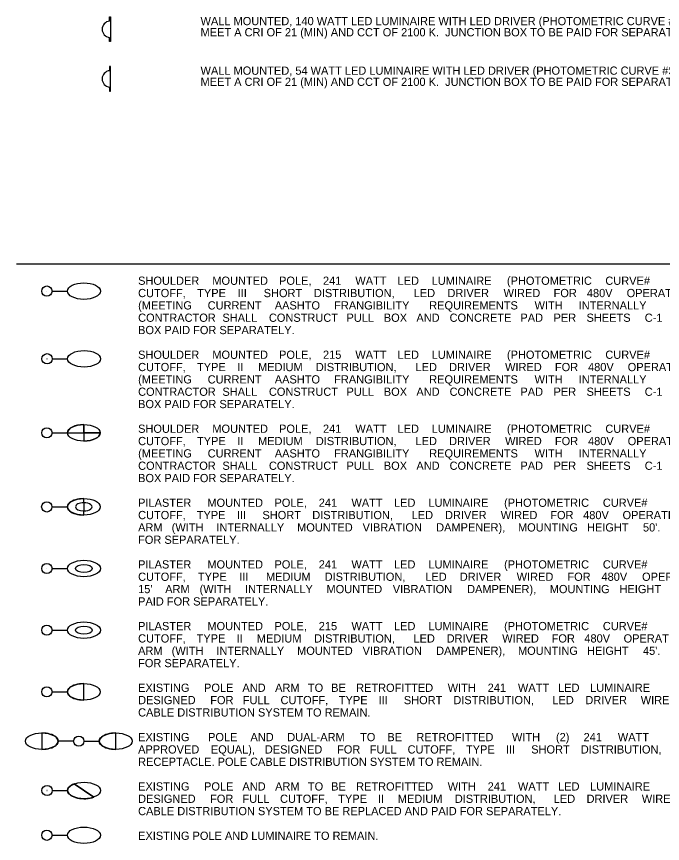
# Model space of a CAD drawing. Extents: x -1500 to -654, y -278 to 331.
# Drawn here: x -1424.2 to -1188.7, y 29.1 to 330.8 of the extents above; entities that cross this region are included whole.
import ezdxf

# ---------------------------------------------------------------- set-up
doc = ezdxf.new("R2010")
doc.units = 0
for name, color, linetype in [('AdhocPoint_dp', 7, 'Continuous'), ('Default', 7, 'Continuous'), ('Logo_dp', 7, 'Continuous'), ('Miscellaneous3', 7, 'Continuous'), ('SheetBorder_dp', 7, 'Continuous'), ('SheetLines_dp', 7, 'Continuous'), ('TextMisc', 7, 'Continuous')]:
    doc.layers.add(name, color=color, linetype=linetype)

msp = doc.modelspace()

# ---------------------------------------------------------------- linework, layer by layer
at = {"layer": 'AdhocPoint_dp'}
for p, q in [((-1390.27, 329.13), (-1390.27, 330.65)), ((-1390.27, 330.65), (-1389.97, 330.65)), ((-1389.97, 330.65), (-1389.97, 321.65)), ((-1390.27, 321.65), (-1390.27, 323.16)), ((-1389.97, 321.65), (-1390.27, 321.65)), ((-1390.27, 312.57), (-1390.27, 311.05)), ((-1389.97, 312.57), (-1390.27, 312.57)), ((-1389.97, 303.57), (-1389.97, 312.57)), ((-1390.27, 305.08), (-1390.27, 303.57)), ((-1390.27, 303.57), (-1389.97, 303.57))]:
    msp.add_line(p, q, dxfattribs=at)
for centre in [(-1389.97, 326.15), (-1389.97, 308.07)]:
    msp.add_arc(centre, 3, 95.7392, 264.2608, dxfattribs=at)
at = {"layer": 'Logo_dp'}
msp.add_line((-1411.26, 32.11), (-1405.63, 32.11), dxfattribs=at)
msp.add_circle((-1413.13, 32.11), 1.88, dxfattribs=at)
msp.add_ellipse((-1399.63, 32.11), major_axis=(6, 0), ratio=0.5, dxfattribs=at)
at = {"layer": 'Miscellaneous3'}
msp.add_line((-1424.17, 240.54), (-654.17, 240.54), dxfattribs=at)
at = {"layer": 'SheetLines_dp'}
for p, q in [((-1413.16, 230.6), (-1413.16, 230.67)), ((-1413.16, 230.67), (-1413.09, 230.67)), ((-1413.09, 230.6), (-1413.16, 230.67)), ((-1413.09, 230.6), (-1413.16, 230.6)), ((-1413.09, 230.67), (-1413.09, 230.6)), ((-1413.08, 205.89), (-1413.08, 205.97)), ((-1413.08, 205.97), (-1413.01, 205.97)), ((-1413.01, 205.89), (-1413.08, 205.97)), ((-1413.01, 205.89), (-1413.08, 205.89)), ((-1413.01, 205.97), (-1413.01, 205.89)), ((-1413.16, 129.39), (-1413.16, 129.47)), ((-1413.16, 129.47), (-1413.09, 129.47)), ((-1413.09, 129.39), (-1413.16, 129.47)), ((-1413.09, 129.39), (-1413.16, 129.39)), ((-1413.09, 129.47), (-1413.09, 129.39)), ((-1413.16, 106.89), (-1413.16, 106.97)), ((-1413.16, 106.97), (-1413.09, 106.97)), ((-1413.09, 106.89), (-1413.16, 106.97)), ((-1413.09, 106.89), (-1413.16, 106.89)), ((-1413.09, 106.97), (-1413.09, 106.89)), ((-1413.08, 48.39), (-1413.08, 48.47)), ((-1413.08, 48.47), (-1413.01, 48.47)), ((-1413.01, 48.39), (-1413.08, 48.47)), ((-1413.01, 48.39), (-1413.08, 48.39)), ((-1413.01, 48.47), (-1413.01, 48.39))]:
    msp.add_line(p, q, dxfattribs=at)
at = {"layer": 'TextMisc'}
for p, q in [((-1411.25, 230.63), (-1405.63, 230.63)), ((-1411.17, 205.93), (-1405.55, 205.93)), ((-1399.64, 181.93), (-1399.64, 175.93)), ((-1399.64, 178.93), (-1399.64, 181.93)), ((-1411.25, 178.93), (-1405.63, 178.93)), ((-1405.63, 178.93), (-1393.65, 178.93)), ((-1405.63, 178.93), (-1399.64, 178.93)), ((-1393.65, 178.93), (-1399.64, 178.93)), ((-1399.64, 178.93), (-1399.64, 175.93)), ((-1399.67, 153.43), (-1399.67, 154.93)), ((-1411.29, 151.91), (-1405.66, 151.92)), ((-1399.67, 153.43), (-1399.66, 150.43)), ((-1399.66, 148.93), (-1399.66, 150.43)), ((-1411.25, 129.43), (-1405.63, 129.43)), ((-1411.25, 106.93), (-1405.63, 106.93)), ((-1399.64, 81.43), (-1399.64, 87.43)), ((-1411.25, 84.43), (-1405.63, 84.43)), ((-1414.98, 69.43), (-1414.98, 63.43)), ((-1388.01, 63.43), (-1388.01, 69.43)), ((-1403.37, 66.43), (-1408.99, 66.43)), ((-1399.62, 66.43), (-1394, 66.43)), ((-1411.17, 48.43), (-1405.55, 48.43)), ((-1403.11, 50.84), (-1395.98, 46.02)), ((-1395.98, 46.02), (-1403.11, 50.84))]:
    msp.add_line(p, q, dxfattribs=at)
for centre in [(-1413.13, 230.63), (-1413.05, 205.93), (-1413.13, 178.93), (-1413.16, 151.91), (-1413.13, 129.43), (-1413.13, 106.93), (-1413.13, 84.43), (-1401.49, 66.43), (-1401.49, 66.43), (-1413.05, 48.43)]:
    msp.add_circle(centre, 1.88, dxfattribs=at)
for centre, major_axis in [((-1399.63, 230.63), (6, 0)), ((-1399.55, 205.93), (6, 0)), ((-1399.64, 178.93), (5.99, 0)), ((-1399.66, 151.93), (6, 0.01)), ((-1399.63, 129.43), (6, 0)), ((-1399.63, 129.43), (3, 0)), ((-1399.63, 106.93), (6, 0)), ((-1399.63, 106.93), (3, 0)), ((-1399.63, 106.93), (3, 0)), ((-1399.64, 84.43), (5.99, 0)), ((-1414.98, 66.43), (-5.99, 0)), ((-1388.01, 66.43), (5.99, 0)), ((-1399.55, 48.43), (6, 0))]:
    msp.add_ellipse(centre, major_axis=major_axis, ratio=0.5, dxfattribs=at)
for centre, major_axis, start_param, end_param in [((-1399.64, 178.93), (5.99, 0), 1.570796, 3.141593), ((-1399.64, 178.93), (5.99, 0), 4.712389, 6.283185), ((-1399.66, 151.93), (6, 0.01), 1.570796, 4.712389), ((-1399.66, 151.93), (3, 0), 1.570796, 3.141593), ((-1399.66, 151.93), (3, 0), 3.141593, 4.712389), ((-1399.66, 151.93), (3, 0), 4.712389, 7.853982), ((-1399.64, 84.43), (5.99, 0), 1.570796, 4.712389), ((-1414.98, 66.43), (-5.99, 0), 1.570796, 4.712389), ((-1388.01, 66.43), (5.99, 0), 1.570796, 4.712389), ((-1399.55, 48.43), (6, 0), 2.207405, 5.348998)]:
    msp.add_ellipse(centre, major_axis=major_axis, ratio=0.5, start_param=start_param, end_param=end_param, dxfattribs=at)

# ---------------------------------------------------------------- texts
at = {"layer": 'Default'}
for s, p in [('WALL MOUNTED, 140 WATT LED LUMINAIRE WITH LED DRIVER (PHOTOMETRIC CURVE #S080715T40006 OR APPROVED EQUAL), WIRED FOR 480 VOLT OPERATION. THE LAMP SOURCE MUST ', (-1357.1, 327.65)), ('MEET A CRI OF 21 (MIN) AND CCT OF 2100 K.  JUNCTION BOX TO BE PAID FOR SEPARATELY. ', (-1357.1, 323.58)), ('WALL MOUNTED, 54 WATT LED LUMINAIRE WITH LED DRIVER (PHOTOMETRIC CURVE #S080715T40002 OR APPROVED EQUAL), WIRED FOR 480 VOLT OPERATION. THE LAMP SOURCE MUST ', (-1357.1, 309.57)), ('MEET A CRI OF 21 (MIN) AND CCT OF 2100 K.  JUNCTION BOX TO BE PAID FOR SEPARATELY. ', (-1357.1, 305.5))]:
    msp.add_text(s, height=3, dxfattribs=at).set_placement(p)
at = {"layer": 'SheetBorder_dp'}
for s, p in [('SHOULDER ', (-1379.86, 232.93)), ('MOUNTED ', (-1352.8, 232.93)), ('POLE, ', (-1328.47, 232.93)), ('241 ', (-1312.46, 232.93)), ('WATT ', (-1300.68, 232.93)), ('LED ', (-1285.28, 232.93)), ('LUMINAIRE ', (-1272.86, 232.93)), ('(PHOTOMETRIC ', (-1245.41, 232.93)), ('CURVE# ', (-1209.54, 232.93)), ('CUTOFF, ', (-1379.86, 228.43)), ('TYPE ', (-1358.33, 228.43)), ('III ', (-1343.56, 228.43)), ('SHORT ', (-1334.09, 228.43)), ('DISTRIBUTION, ', (-1315.78, 228.43)), ('LED ', (-1279.39, 228.43)), ('DRIVER ', (-1267.1, 228.43)), ('WIRED ', (-1246.64, 228.43)), ('FOR ', (-1228.41, 228.43)), ('480V ', (-1216.28, 228.43)), ('OPERATION, ', (-1201.77, 228.43)), ('(MEETING ', (-1379.86, 223.93)), ('CURRENT ', (-1354.5, 223.93)), ('AASHTO ', (-1330.04, 223.93)), ('FRANGIBILITY ', (-1308.39, 223.93)), ('REQUIREMENTS ', (-1273.74, 223.93)), ('WITH ', (-1235.34, 223.93)), ('INTERNALLY ', (-1219.27, 223.93)), ('CONTRACTOR ', (-1379.86, 219.43)), ('SHALL ', (-1349.13, 219.43)), ('CONSTRUCT ', (-1332.18, 219.43)), ('PULL ', (-1303.9, 219.43)), ('BOX ', (-1290.29, 219.43)), ('AND ', (-1278.42, 219.43)), ('CONCRETE ', (-1266.32, 219.43)), ('PAD ', (-1240.5, 219.43)), ('PER ', (-1228.42, 219.43)), ('SHEETS ', (-1216.39, 219.43)), ('C-1 ', (-1195.18, 219.43)), ('BOX PAID FOR SEPARATELY.', (-1379.86, 214.93)), ('SHOULDER ', (-1379.86, 205.93)), ('MOUNTED ', (-1352.8, 205.93)), ('POLE, ', (-1328.47, 205.93)), ('215 ', (-1312.46, 205.93)), ('WATT ', (-1300.68, 205.93)), ('LED ', (-1285.28, 205.93)), ('LUMINAIRE ', (-1272.86, 205.93)), ('(PHOTOMETRIC ', (-1245.41, 205.93)), ('CURVE# ', (-1209.54, 205.93)), ('CUTOFF, ', (-1379.86, 201.43)), ('TYPE ', (-1358.39, 201.43)), ('II ', (-1343.67, 201.43)), ('MEDIUM ', (-1336.14, 201.43)), ('DISTRIBUTION, ', (-1315.08, 201.43)), ('LED ', (-1278.74, 201.43)), ('DRIVER ', (-1266.5, 201.43)), ('WIRED ', (-1246.09, 201.43)), ('FOR ', (-1227.92, 201.43)), ('480V ', (-1215.85, 201.43)), ('OPERATION, ', (-1201.39, 201.43)), ('(MEETING ', (-1379.86, 196.93)), ('CURRENT ', (-1354.5, 196.93)), ('AASHTO ', (-1330.04, 196.93)), ('FRANGIBILITY ', (-1308.39, 196.93)), ('REQUIREMENTS ', (-1273.74, 196.93)), ('WITH ', (-1235.34, 196.93)), ('INTERNALLY ', (-1219.27, 196.93)), ('CONTRACTOR ', (-1379.86, 192.43)), ('SHALL ', (-1349.13, 192.43)), ('CONSTRUCT ', (-1332.18, 192.43)), ('PULL ', (-1303.9, 192.43)), ('BOX ', (-1290.29, 192.43)), ('AND ', (-1278.42, 192.43)), ('CONCRETE ', (-1266.32, 192.43)), ('PAD ', (-1240.5, 192.43)), ('PER ', (-1228.42, 192.43)), ('SHEETS ', (-1216.39, 192.43)), ('C-1 ', (-1195.18, 192.43)), ('BOX PAID FOR SEPARATELY.', (-1379.86, 187.93)), ('SHOULDER ', (-1379.86, 178.93)), ('MOUNTED ', (-1352.8, 178.93)), ('POLE, ', (-1328.47, 178.93)), ('241 ', (-1312.46, 178.93)), ('WATT ', (-1300.68, 178.93)), ('LED ', (-1285.28, 178.93)), ('LUMINAIRE ', (-1272.86, 178.93)), ('(PHOTOMETRIC ', (-1245.41, 178.93)), ('CURVE# ', (-1209.54, 178.93)), ('CUTOFF, ', (-1379.86, 174.43)), ('TYPE ', (-1358.39, 174.43)), ('II ', (-1343.67, 174.43)), ('MEDIUM ', (-1336.14, 174.43)), ('DISTRIBUTION, ', (-1315.08, 174.43)), ('LED ', (-1278.74, 174.43)), ('DRIVER ', (-1266.5, 174.43)), ('WIRED ', (-1246.09, 174.43)), ('FOR ', (-1227.92, 174.43)), ('480V ', (-1215.85, 174.43)), ('OPERATION, ', (-1201.39, 174.43)), ('(MEETING ', (-1379.86, 169.93)), ('CURRENT ', (-1354.5, 169.93)), ('AASHTO ', (-1330.04, 169.93)), ('FRANGIBILITY ', (-1308.39, 169.93)), ('REQUIREMENTS ', (-1273.74, 169.93)), ('WITH ', (-1235.34, 169.93)), ('INTERNALLY ', (-1219.27, 169.93)), ('CONTRACTOR ', (-1379.86, 165.43)), ('SHALL ', (-1349.13, 165.43)), ('CONSTRUCT ', (-1332.18, 165.43)), ('PULL ', (-1303.9, 165.43)), ('BOX ', (-1290.29, 165.43)), ('AND ', (-1278.42, 165.43)), ('CONCRETE ', (-1266.32, 165.43)), ('PAD ', (-1240.5, 165.43)), ('PER ', (-1228.42, 165.43)), ('SHEETS ', (-1216.39, 165.43)), ('C-1 ', (-1195.18, 165.43)), ('BOX PAID FOR SEPARATELY.', (-1379.86, 160.93)), ('PILASTER ', (-1379.86, 151.93)), ('MOUNTED ', (-1354.61, 151.93)), ('POLE, ', (-1330.15, 151.93)), ('241 ', (-1314.01, 151.93)), ('WATT ', (-1302.1, 151.93)), ('LED ', (-1286.57, 151.93)), ('LUMINAIRE ', (-1274.03, 151.93)), ('(PHOTOMETRIC ', (-1246.45, 151.93)), ('CURVE# ', (-1210.45, 151.93)), ('CUTOFF, ', (-1379.86, 147.43)), ('TYPE ', (-1358.48, 147.43)), ('III ', (-1343.86, 147.43)), ('SHORT ', (-1334.53, 147.43)), ('DISTRIBUTION, ', (-1316.38, 147.43)), ('LED ', (-1280.14, 147.43)), ('DRIVER ', (-1267.99, 147.43)), ('WIRED ', (-1247.68, 147.43)), ('FOR ', (-1229.61, 147.43)), ('480V ', (-1217.63, 147.43)), ('OPERATION ', (-1203.27, 147.43)), ('ARM ', (-1379.86, 142.93)), ('(WITH ', (-1367.62, 142.93)), ('INTERNALLY ', (-1351.34, 142.93)), ('MOUNTED ', (-1321.91, 142.93)), ('VIBRATION ', (-1298.03, 142.93)), ('DAMPENER), ', (-1271.22, 142.93)), ('MOUNTING ', (-1241.38, 142.93)), ('HEIGHT ', (-1216.23, 142.93)), ("50'. ", (-1195.82, 142.93)), ('FOR SEPARATELY.', (-1379.86, 138.43)), ('PILASTER ', (-1379.86, 129.43)), ('MOUNTED ', (-1354.61, 129.43)), ('POLE, ', (-1330.15, 129.43)), ('241 ', (-1314.01, 129.43)), ('WATT ', (-1302.1, 129.43)), ('LED ', (-1286.57, 129.43)), ('LUMINAIRE ', (-1274.03, 129.43)), ('(PHOTOMETRIC ', (-1246.45, 129.43)), ('CURVE# ', (-1210.45, 129.43)), ('CUTOFF, ', (-1379.86, 124.93)), ('TYPE ', (-1358.05, 124.93)), ('III ', (-1343, 124.93)), ('MEDIUM ', (-1333.25, 124.93)), ('DISTRIBUTION, ', (-1311.85, 124.93)), ('LED ', (-1275.18, 124.93)), ('DRIVER ', (-1262.6, 124.93)), ('WIRED ', (-1241.86, 124.93)), ('FOR ', (-1223.36, 124.93)), ('480V ', (-1210.95, 124.93)), ('OPERATION, ', (-1196.16, 124.93)), ("15' ", (-1379.86, 120.43)), ('ARM ', (-1369.98, 120.43)), ('(WITH ', (-1357.45, 120.43)), ('INTERNALLY ', (-1340.9, 120.43)), ('MOUNTED ', (-1311.18, 120.43)), ('VIBRATION ', (-1287.02, 120.43)), ('DAMPENER), ', (-1259.93, 120.43)), ('MOUNTING ', (-1229.81, 120.43)), ('HEIGHT ', (-1204.37, 120.43)), ('PAID FOR SEPARATELY.', (-1379.86, 115.93)), ('PILASTER ', (-1379.86, 106.93)), ('MOUNTED ', (-1354.61, 106.93)), ('POLE, ', (-1330.15, 106.93)), ('215 ', (-1314.01, 106.93)), ('WATT ', (-1302.1, 106.93)), ('LED ', (-1286.57, 106.93)), ('LUMINAIRE ', (-1274.03, 106.93)), ('(PHOTOMETRIC ', (-1246.45, 106.93)), ('CURVE# ', (-1210.45, 106.93)), ('CUTOFF, ', (-1379.86, 102.43)), ('TYPE ', (-1358.54, 102.43)), ('II ', (-1343.97, 102.43)), ('MEDIUM ', (-1336.59, 102.43)), ('DISTRIBUTION, ', (-1315.68, 102.43)), ('LED ', (-1279.49, 102.43)), ('DRIVER ', (-1267.4, 102.43)), ('WIRED ', (-1247.14, 102.43)), ('FOR ', (-1229.12, 102.43)), ('480V ', (-1217.19, 102.43)), ('OPERATION, ', (-1202.89, 102.43)), ('ARM ', (-1379.86, 97.93)), ('(WITH ', (-1367.62, 97.93)), ('INTERNALLY ', (-1351.34, 97.93)), ('MOUNTED ', (-1321.91, 97.93)), ('VIBRATION ', (-1298.03, 97.93)), ('DAMPENER), ', (-1271.22, 97.93)), ('MOUNTING ', (-1241.38, 97.93)), ('HEIGHT ', (-1216.23, 97.93)), ("45'. ", (-1195.82, 97.93)), ('FOR SEPARATELY.', (-1379.86, 93.43)), ('EXISTING ', (-1379.86, 84.43)), ('POLE ', (-1355.83, 84.43)), ('AND ', (-1341.85, 84.43)), ('ARM ', (-1329.91, 84.43)), ('TO ', (-1317.97, 84.43)), ('BE ', (-1309.48, 84.43)), ('RETROFITTED ', (-1300.39, 84.43)), ('WITH ', (-1267, 84.43)), ('241 ', (-1252.43, 84.43)), ('WATT ', (-1241.4, 84.43)), ('LED ', (-1226.76, 84.43)), ('LUMINAIRE ', (-1215.09, 84.43)), ('DESIGNED ', (-1379.86, 79.93)), ('FOR ', (-1353.56, 79.93)), ('FULL ', (-1341.7, 79.93)), ('CUTOFF, ', (-1327.95, 79.93)), ('TYPE ', (-1306.69, 79.93)), ('III ', (-1292.19, 79.93)), ('SHORT ', (-1282.99, 79.93)), ('DISTRIBUTION, ', (-1264.96, 79.93)), ('LED ', (-1228.84, 79.93)), ('DRIVER ', (-1216.82, 79.93)), ('WIRED ', (-1196.63, 79.93)), ('CABLE DISTRIBUTION SYSTEM TO REMAIN.', (-1379.86, 75.43)), ('EXISTING ', (-1379.86, 66.43)), ('POLE ', (-1354.36, 66.43)), ('AND ', (-1338.91, 66.43)), ('DUAL-ARM ', (-1325.5, 66.43)), ('TO ', (-1298.95, 66.43)), ('BE ', (-1289, 66.43)), ('RETROFITTED ', (-1278.43, 66.43)), ('WITH ', (-1243.58, 66.43)), ('(2) ', (-1227.54, 66.43)), ('241 ', (-1217.48, 66.43)), ('WATT ', (-1204.98, 66.43)), ('APPROVED ', (-1379.86, 61.93)), ('EQUAL), ', (-1353.33, 61.93)), ('DESIGNED ', (-1333.67, 61.93)), ('FOR ', (-1307.33, 61.93)), ('FULL ', (-1295.43, 61.93)), ('CUTOFF, ', (-1281.63, 61.93)), ('TYPE ', (-1260.34, 61.93)), ('III ', (-1245.8, 61.93)), ('SHORT ', (-1236.56, 61.93)), ('DISTRIBUTION, ', (-1218.49, 61.93)), ('RECEPTACLE. POLE CABLE DISTRIBUTION SYSTEM TO REMAIN.', (-1379.86, 57.43)), ('EXISTING ', (-1379.86, 48.43)), ('POLE ', (-1355.83, 48.43)), ('AND ', (-1341.85, 48.43)), ('ARM ', (-1329.91, 48.43)), ('TO ', (-1317.97, 48.43)), ('BE ', (-1309.48, 48.43)), ('RETROFITTED ', (-1300.39, 48.43)), ('WITH ', (-1267, 48.43)), ('241 ', (-1252.43, 48.43)), ('WATT ', (-1241.4, 48.43)), ('LED ', (-1226.76, 48.43)), ('LUMINAIRE ', (-1215.09, 48.43)), ('DESIGNED ', (-1379.86, 43.93)), ('FOR ', (-1353.61, 43.93)), ('FULL ', (-1341.81, 43.93)), ('CUTOFF, ', (-1328.11, 43.93)), ('TYPE ', (-1306.91, 43.93)), ('II ', (-1292.46, 43.93)), ('MEDIUM ', (-1285.2, 43.93)), ('DISTRIBUTION, ', (-1264.41, 43.93)), ('LED ', (-1228.35, 43.93)), ('DRIVER ', (-1216.38, 43.93)), ('WIRED ', (-1196.25, 43.93)), ('CABLE DISTRIBUTION SYSTEM TO BE REPLACED AND PAID FOR SEPARATELY. ', (-1379.86, 39.43)), ('EXISTING POLE AND LUMINAIRE TO REMAIN.', (-1379.86, 30.43))]:
    msp.add_text(s, height=3, dxfattribs=at).set_placement(p)

doc.saveas('drawing.dxf')
